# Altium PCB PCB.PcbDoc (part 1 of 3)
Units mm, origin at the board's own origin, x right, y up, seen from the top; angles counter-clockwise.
Board outline 120 x 100 mm, 4 copper layers (Top Layer, Mid-Layer 1, Mid-Layer 2, Bottom Layer); 85 components, 69 nets, 423 pads, 4470 vias.
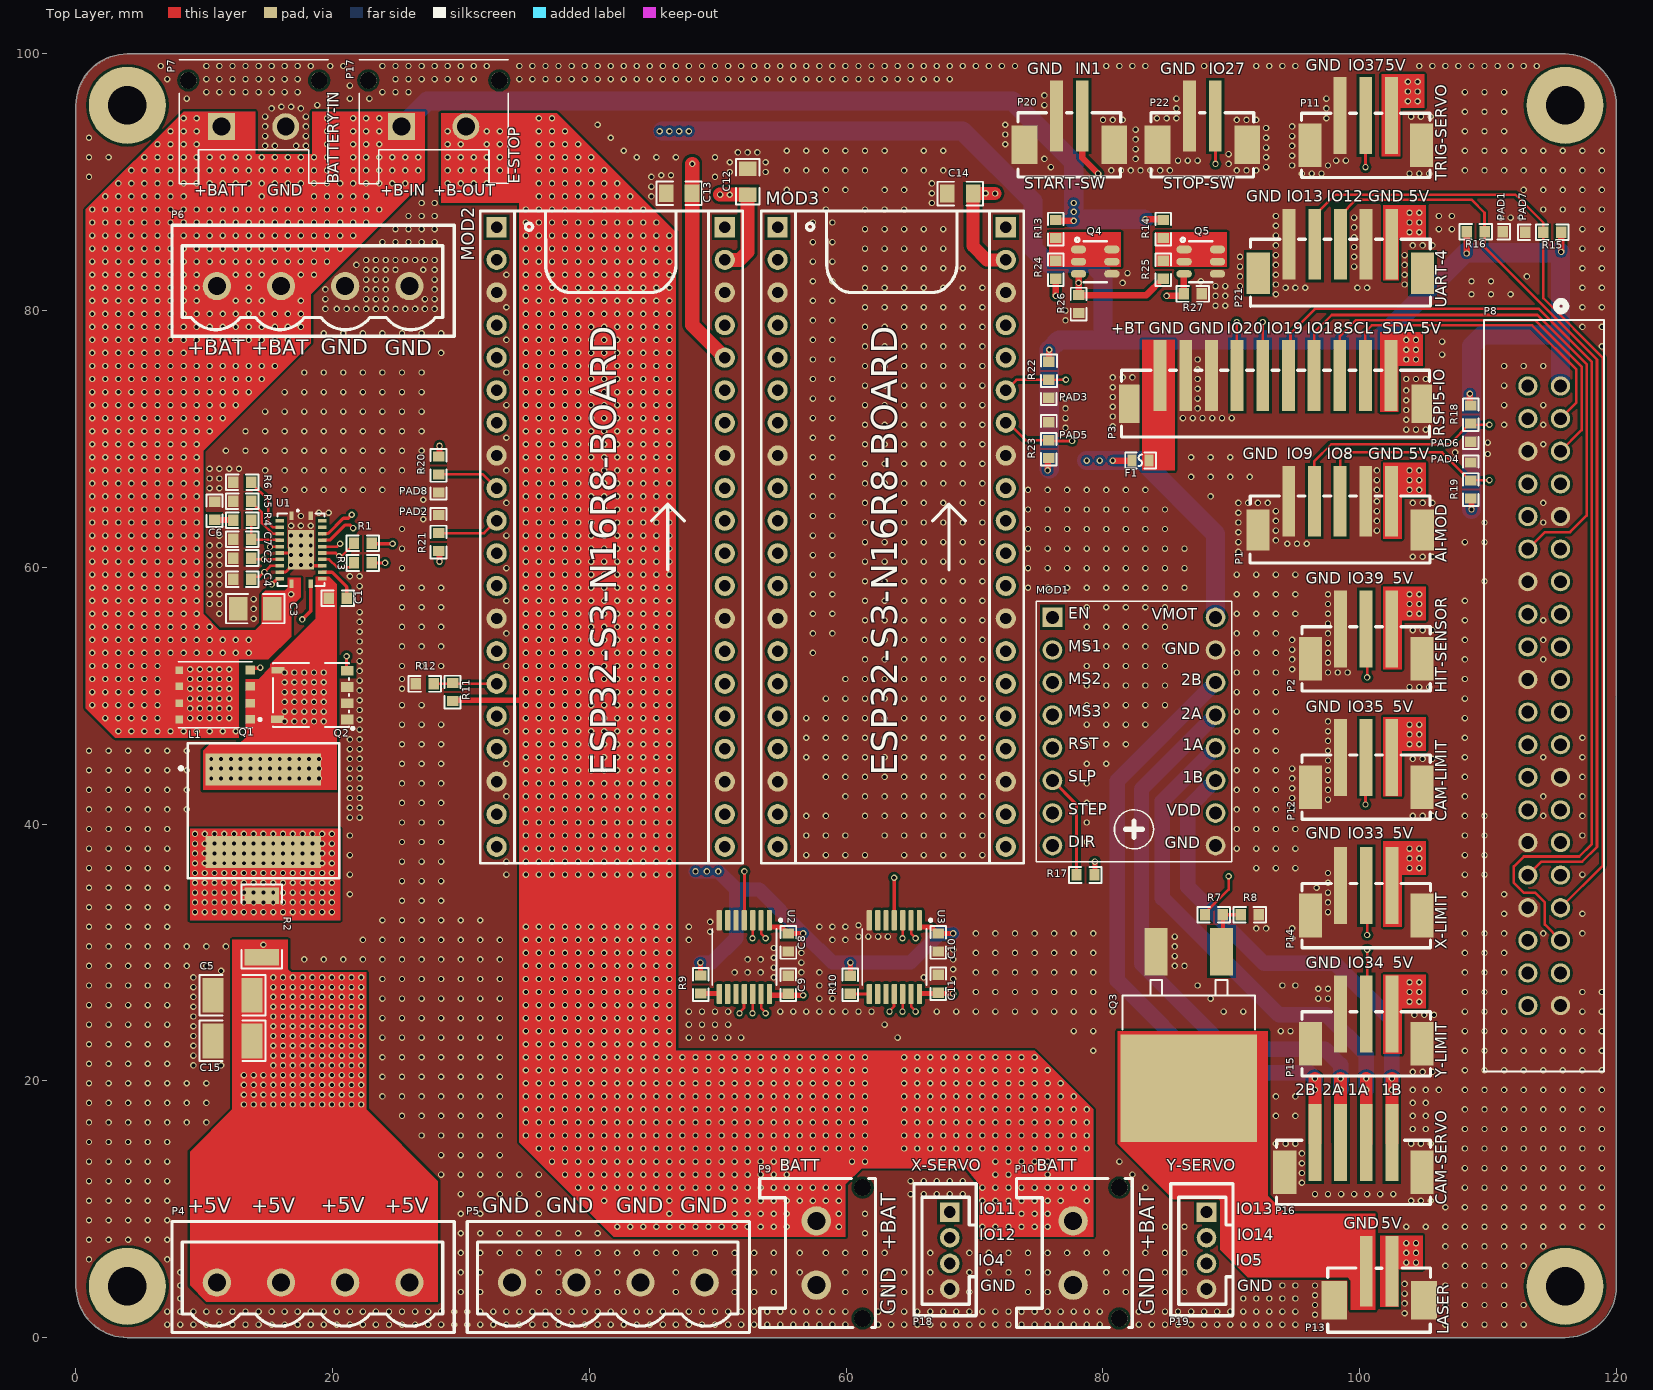
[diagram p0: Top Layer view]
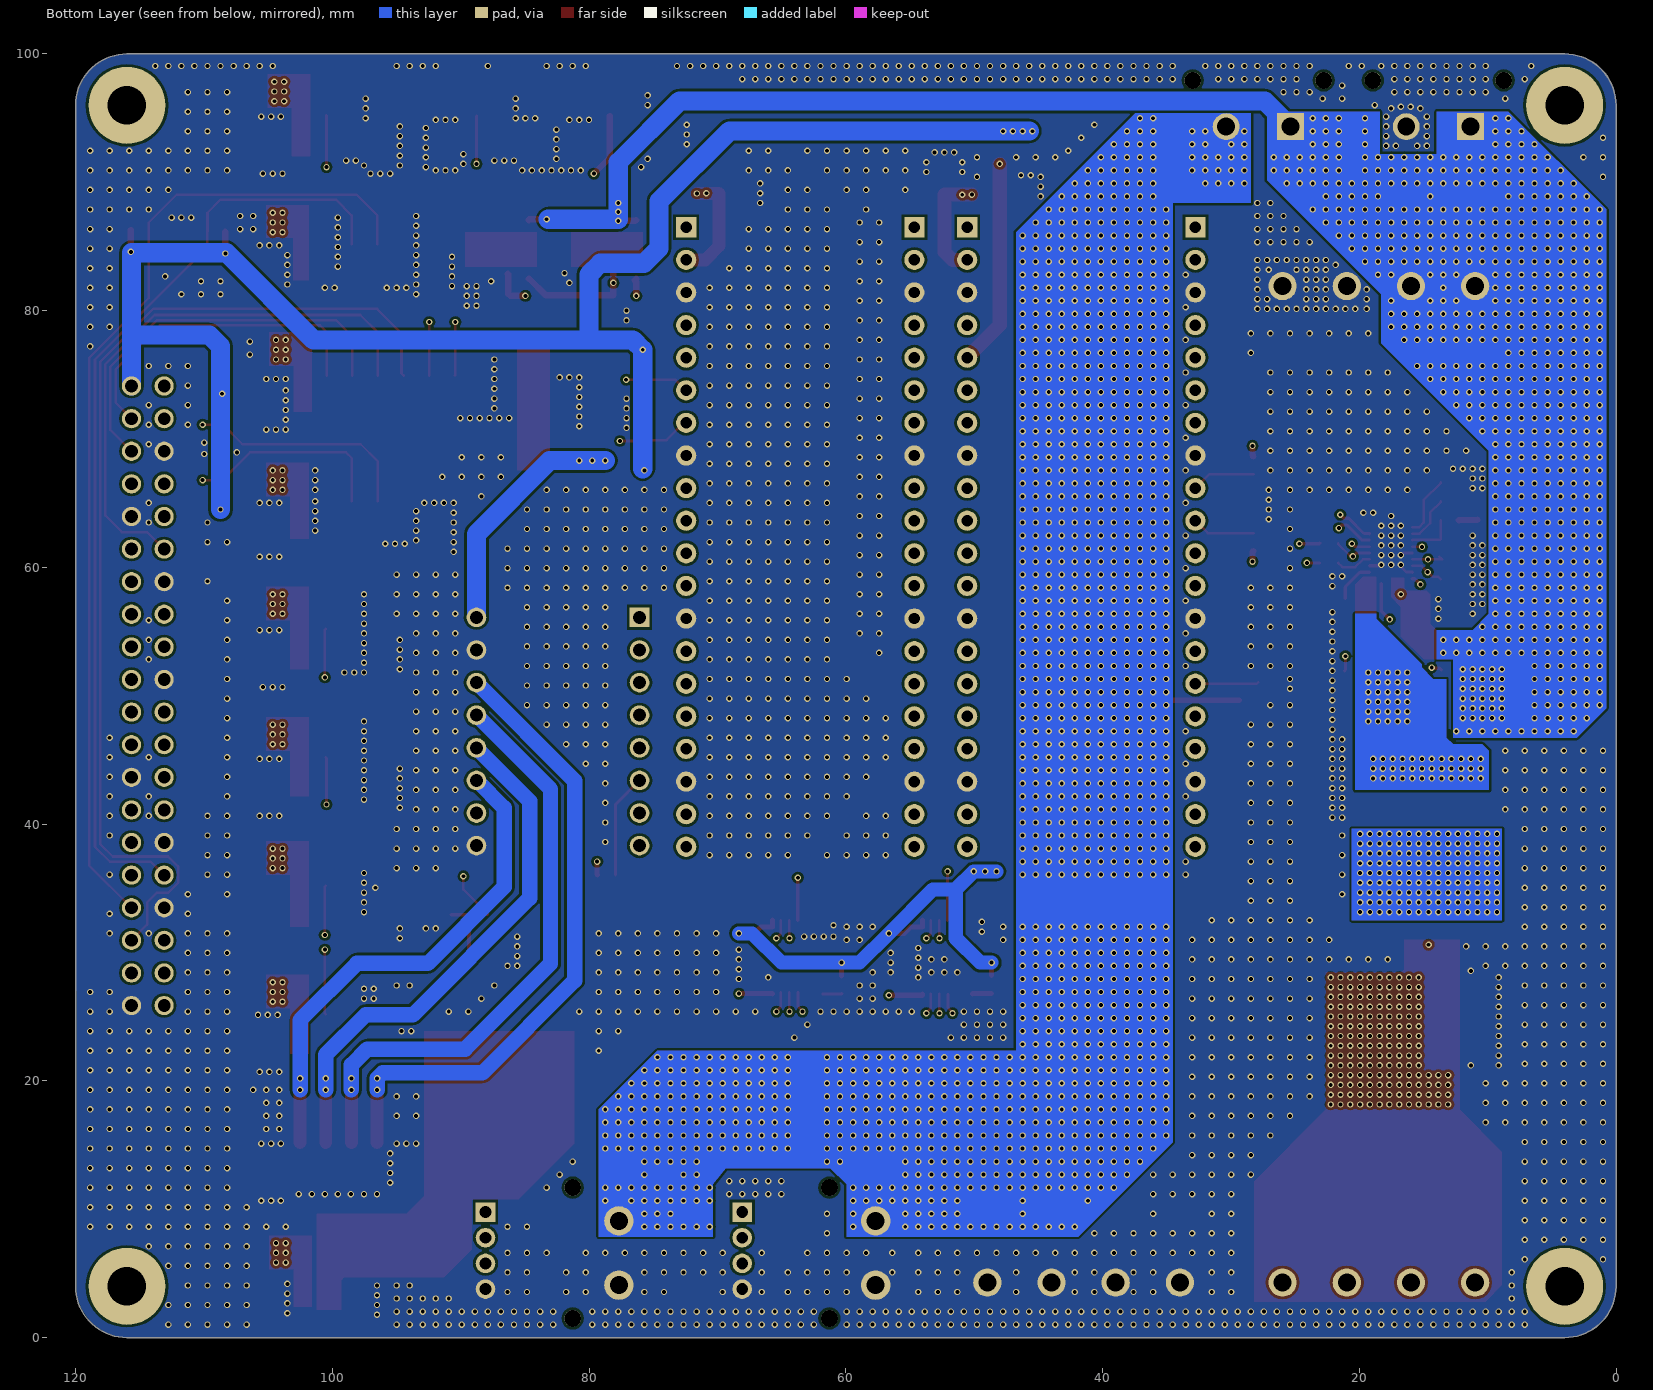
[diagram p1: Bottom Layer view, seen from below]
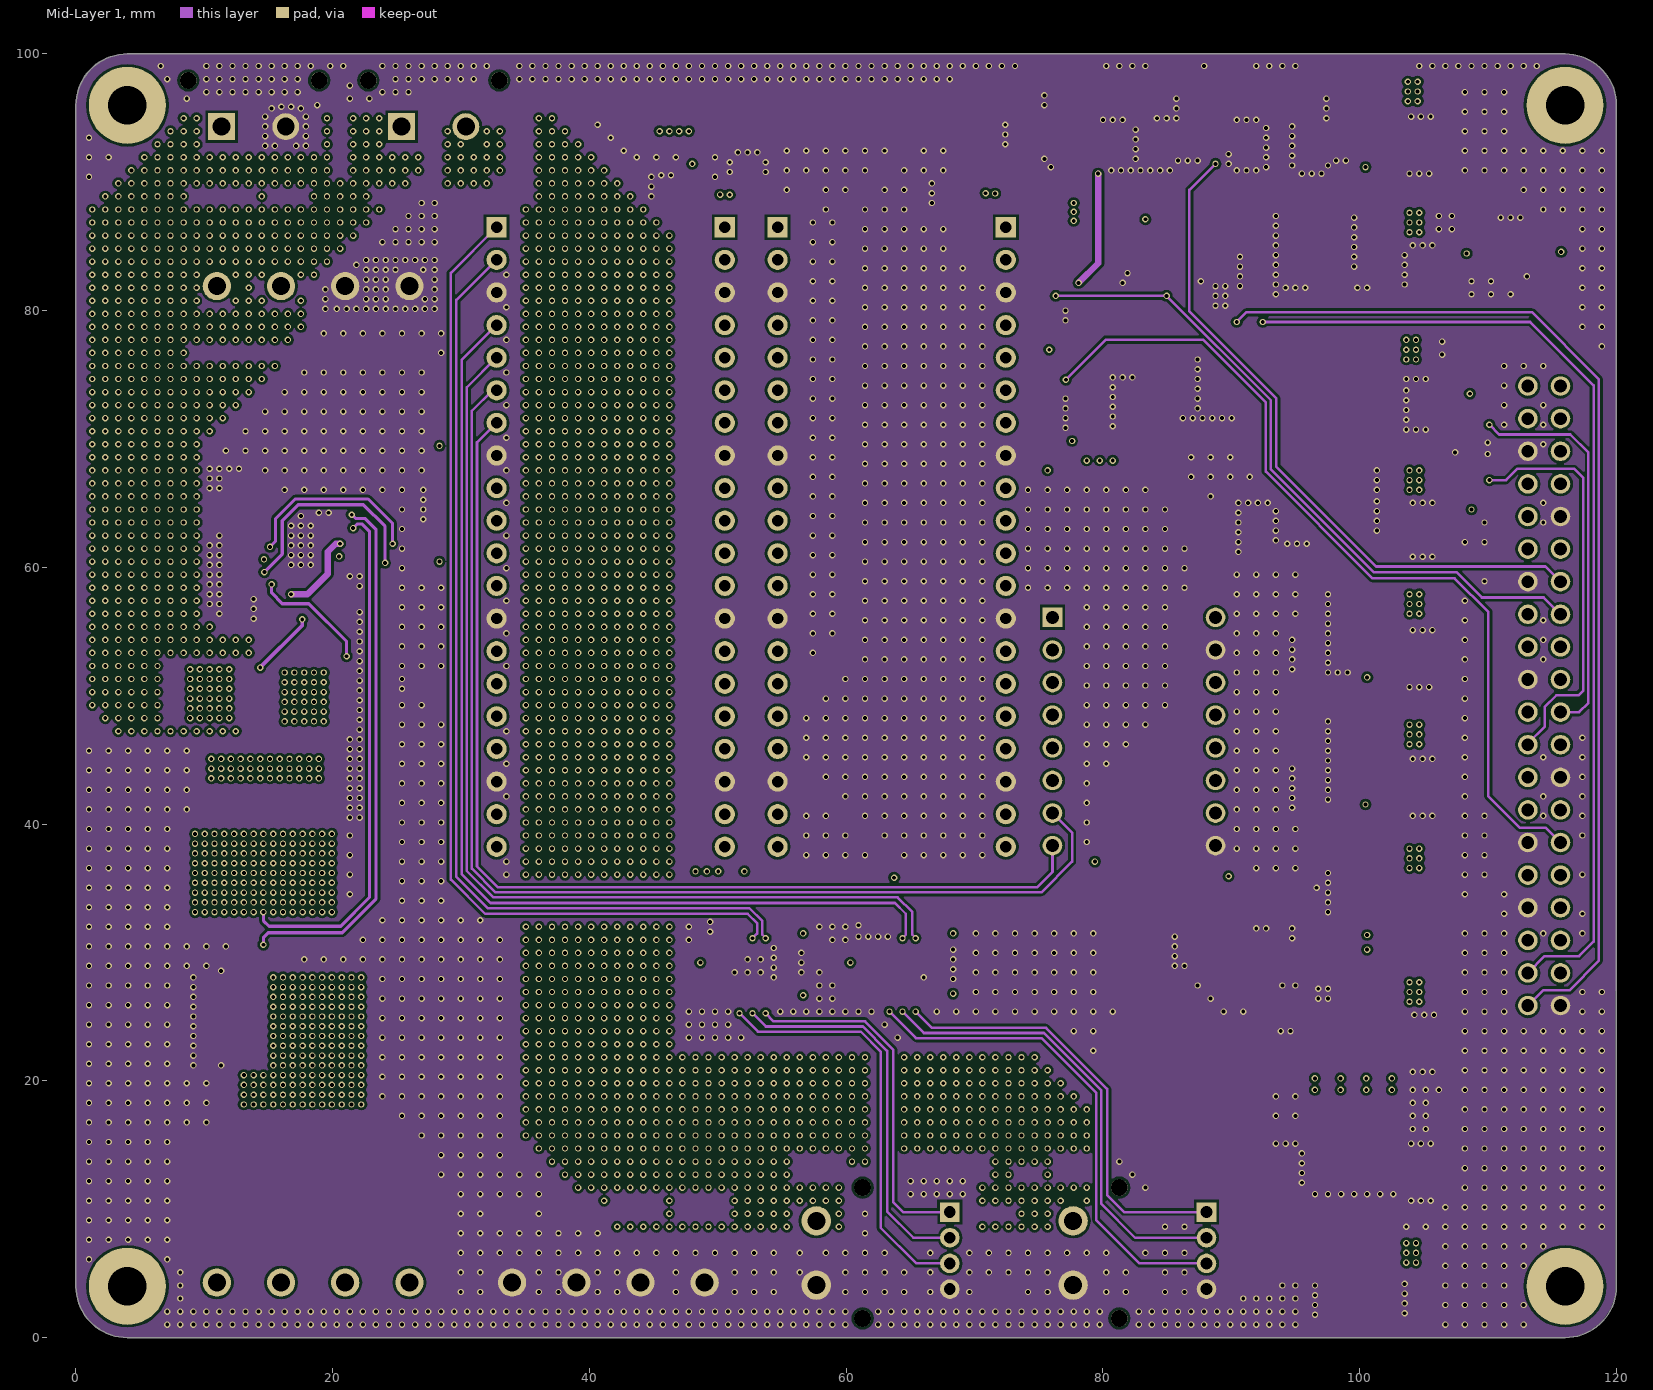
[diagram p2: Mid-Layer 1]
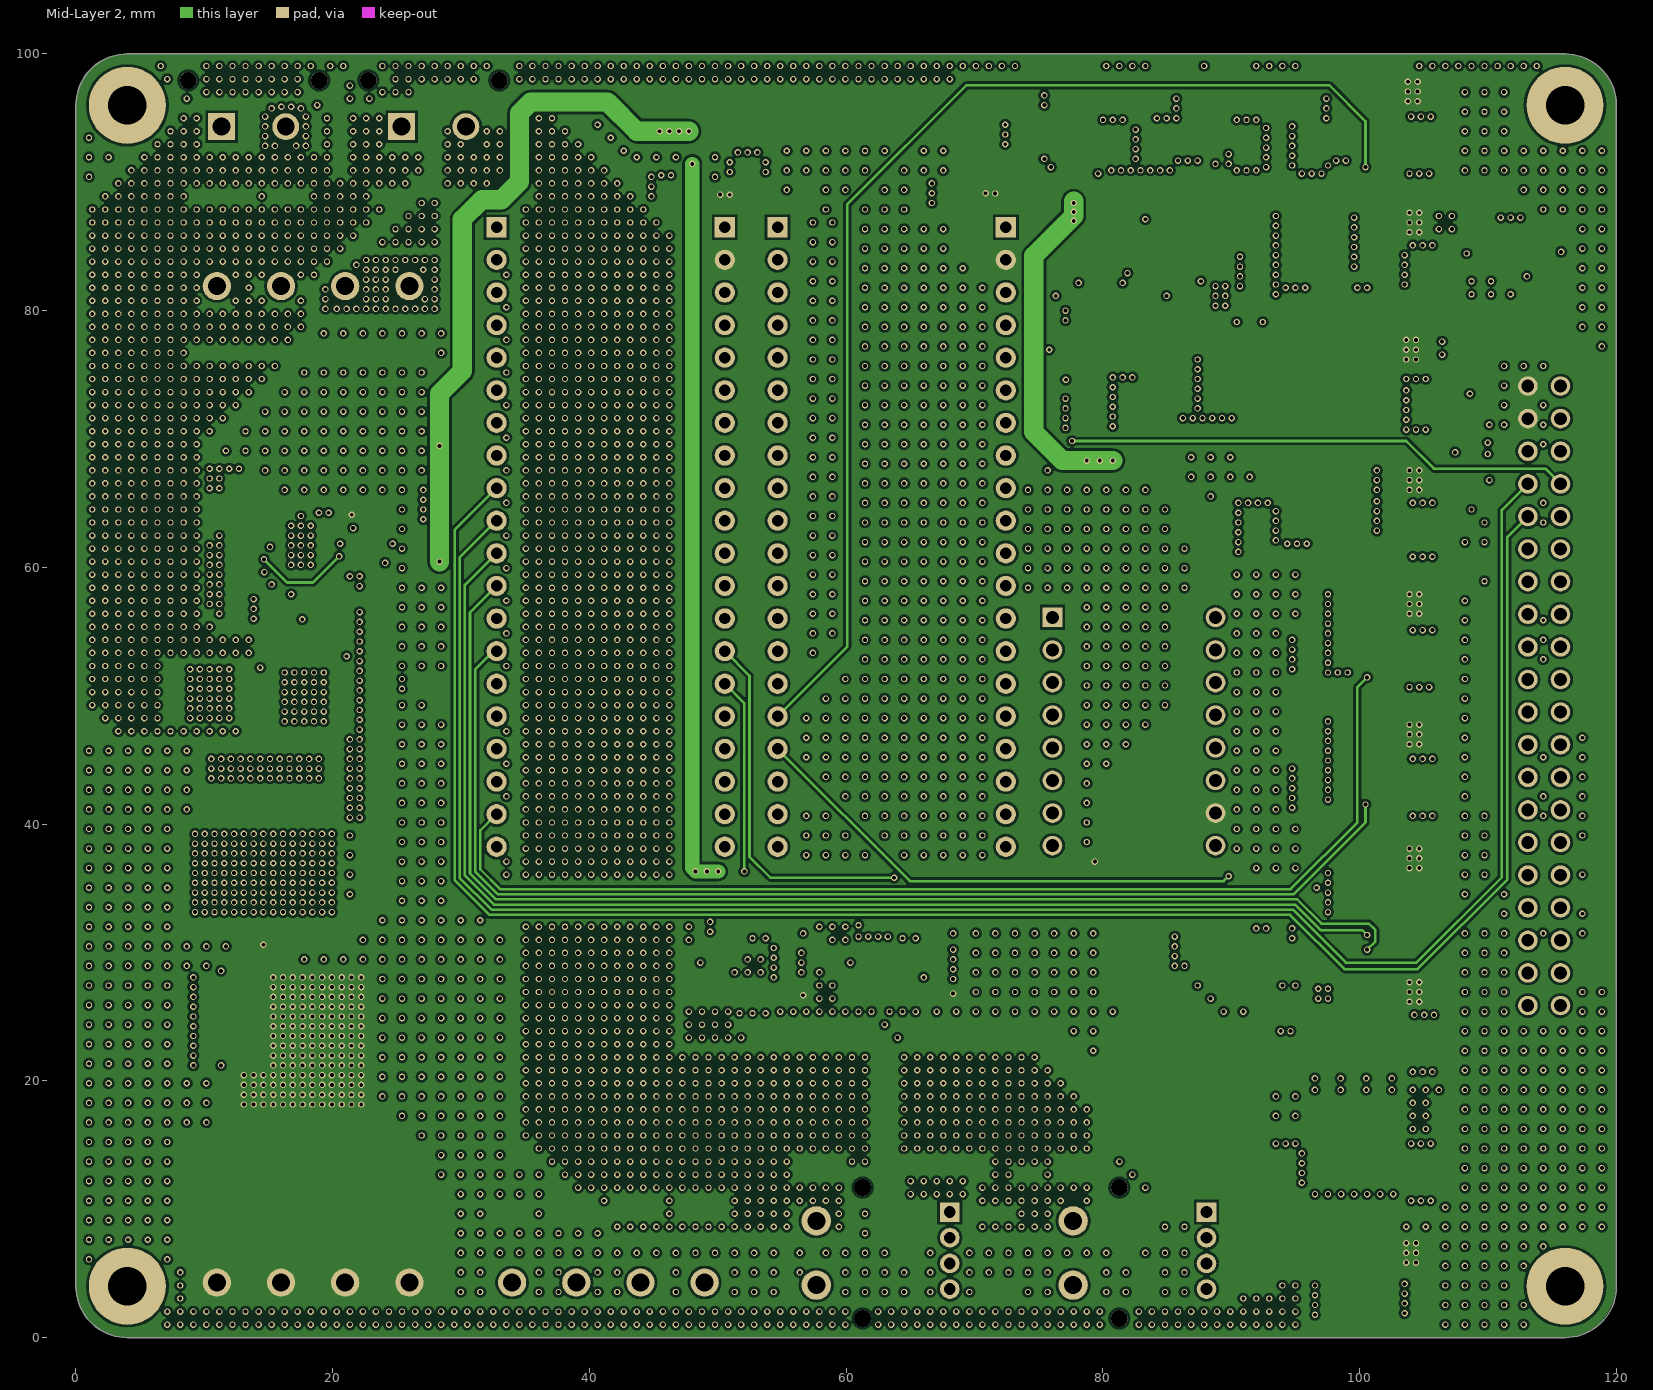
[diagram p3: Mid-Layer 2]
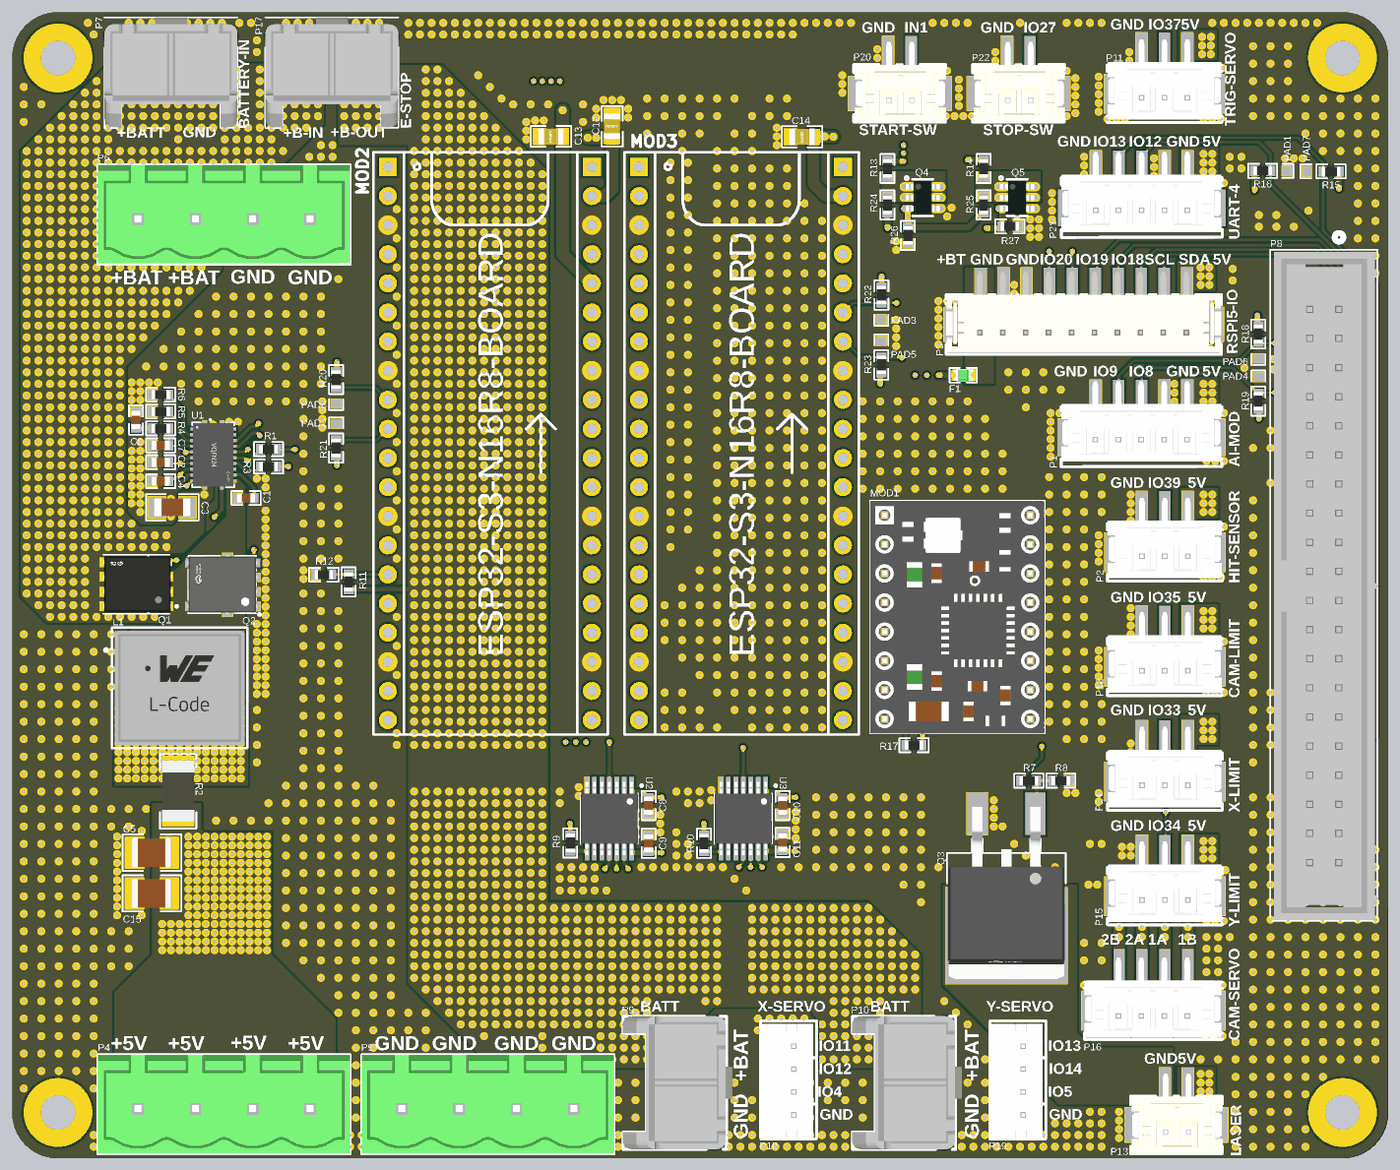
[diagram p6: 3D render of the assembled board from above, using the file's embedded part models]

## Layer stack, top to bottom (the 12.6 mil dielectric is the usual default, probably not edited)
Top Solder: solder mask 0.0102, Solder Resist, Dk 3.5
Top Layer: signal copper 0.0356
Dielectric 1: dielectric 0.32, FR-4, Dk 4.8
Mid-Layer 1: signal copper 0.0356
Dielectric2: dielectric 0.32, FR-4, Dk 4.8
Mid-Layer 2: signal copper 0.0356
Dielectric3: dielectric 0.32, FR-4, Dk 4.8
Bottom Layer: signal copper 0.0356
Bottom Solder: solder mask 0.0102, Solder Resist, Dk 3.5

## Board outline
0,4 0,96 cw(c4,96) 4,100 116,100 cw(c116,96) 120,96 120,4 cw(c116,4) 116,0 4,0 cw(c4,4)

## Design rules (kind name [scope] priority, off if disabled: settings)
Clearance [All] p1: gap=0.2 ignorepadtopadclearanceinfootprint=FALSE except(0: Arc-Hole Track-Hole SMDPad-Hole THPad-Hole Via-Hole Fill-Hole Poly-Hole Region-Hole Text-Hole; 0.18: Fill-Fill Fill-Poly Fill-Region Poly-Poly Poly-Region Region-Region)
HoleSize [All] p1: absolutevalues=TRUE maxlimit=5 minlimit=0.025 maxpercent=80.000 minpercent=20.000
MinimumSolderMaskSliver [All] p1: minsoldermaskwidth=0.007
PlaneClearance [All] p1: clearance=0.4
PolygonConnect [InNet('GND') vs InNet('GND')] p1: connectstyle=Direct reliefconductorwidth=0.254 reliefentries=4 polygonreliefangle="90 Angle" airgapwidth=0.254
PolygonConnect PolygonConnect_1 [InNet('+5V') vs InNet('+5V')] p2: connectstyle=Direct reliefconductorwidth=0.254 reliefentries=4 polygonreliefangle="90 Angle" airgapwidth=0.254
RoutingVias [All] p1: holewidth=0.3 width=0.5 viastyle="Through Hole" minholewidth=0.2 minwidth=0.5 maxholewidth=0.4 maxwidth=0.5
SilkToSilkClearance [All] p1: silktosilkclearance=0.1
SilkToSolderMaskClearance [IsPad] p1: minsilkscreentomaskgap=0.02 clearancetoexposedcopper=TRUE
SolderMaskExpansion [All] p1: expansion=0.102
Width [All] p1: maxlimit=3 minlimit=0.2 preferedwidth=0.254
25 further rules are at their usual default settings.

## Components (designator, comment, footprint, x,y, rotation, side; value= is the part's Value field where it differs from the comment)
C1 "0.1uF/50V" CAP_SMD_0603 20.396,57.607 r0 top
C2 "0.1uF/50V" CAP_SMD_0603 12.954,60.731 r180 top
C3 "4.7uF/100V" CAP_SMD_1206 13.97,56.794 r0 top
C4 "2.2uF" CAP_SMD_0603 12.954,59.08 r0 top
C5 "47uF/16V" CAP_SMD_1210 12.192,26.67 r0 top
C6 "1.5nF" CAP_SMD_0603 10.795,64.414 r90 top
C7 "56pF" CAP_SMD_0603 12.954,62.205 r180 top
C8 "0.1uF/50V" CAP_SMD_0603 55.499,30.785 r90 top
C9 "0.1uF/50V" CAP_SMD_0603 55.499,27.483 r270 top
C10 "0.1uF/50V" CAP_SMD_0603 67.183,30.785 r90 top
C11 "0.1uF/50V" CAP_SMD_0603 67.183,27.559 r270 top
C12 "10uF/16V" CAP_SMD_0805 52.324,90.043 r270 top
C13 "10uF/16V" CAP_SMD_0805 46.99,89.154 r0 top
C14 "10uF/16V" CAP_SMD_0805 68.885,89.129 r0 top
C15 "47uF/16V" CAP_SMD_1210 12.192,23.114 r0 top
F1 "1A/50V" FUSE_SMD_0603 82.931,68.326 r180 top
L1 "1.2uH/23.6A" "IND_SMD_7.90mm x 7.60mm" 14.605,41.046 r0 top
MOD1 "A4988_Module" A4988_Stepper_Motor_Module 82.423,47.219 r0 top
MOD2 "ESP32-S3-Pico-Module" ESP32-S3-PICO_Module 41.656,62.37 r0 top
MOD3 "ESP32-S3-Pico-Module" ESP32-S3-PICO_Module 63.55,62.37 r0 top
P1 "AI MOD" CONN_Header_SMD_Vertical_5P_2MM_B5B-PH-SM4-TB 98.477,64.043 r180 top
P2 "HIT_SENSOR" CONN_Header_SMD_Vertical_3P_2MM_B3B-PH-SM4-TB 100.508,54.043 r180 top
P3 "IO" CONN_Header_SMD_Vertical_10P_2MM_B10B-PH-SM4-TB 93.451,73.855 r180 top
P4 "5V" CONN_Terminal_Block_Header_4P_Vertical__THT_5.00mm_1755532 18.477,4.293 r0 top
P5 "5V" CONN_Terminal_Block_Header_4P_Vertical__THT_5.00mm_1755532 41.477,4.293 r0 top
P6 "BATT" CONN_Terminal_Block_Header_4P_Vertical__THT_5.00mm_1755532 18.477,81.915 r0 top
P7 "BATT" CONN_HEADER_VERT_2POS_5MM_1-1376382-2 13.843,96.139 r0 top
P8 "RPI-5" CONN_HEADERTHT_IDE_40P_2.54mm 114.376,50 r270 top
P9 "BATT" CONN_HEADER_VERT_2POS_5MM_2-1376382-3 59.477,6.593 r90 top
P10 "BATT" CONN_HEADER_VERT_2POS_5MM_2-1376382-3 79.477,6.593 r90 top
P11 "TRIGGER_SERVO" CONN_Header_SMD_Vertical_3P_2MM_B3B-PH-SM4-TB 100.476,94.043 r180 top
P12 "CAM-LIMIT" CONN_Header_SMD_Vertical_3P_2MM_B3B-PH-SM4-TB 100.508,44.043 r180 top
P13 "LASER" CONN_Header_SMD_Vertical_2P_2MM_B2B-PH-SM4-TB 101.514,4.043 r180 top
P14 "X-LIMIT" CONN_Header_SMD_Vertical_3P_2MM_B3B-PH-SM4-TB 100.514,34.043 r180 top
P15 "Y-LIMIT" CONN_Header_SMD_Vertical_3P_2MM_B3B-PH-SM4-TB 100.514,24.043 r180 top
P16 "CAM_SERVO" CONN_Header_SMD_Vertical_4P_2MM_B4B-PH-SM4-TB 99.517,14.043 r180 top
P17 "ESTOP" CONN_HEADER_VERT_2POS_5MM_1-1376382-2 27.875,96.139 r0 top
P18 "X-SERVO" CONN_Header_Through_Hole_4P_2MM_B4B-PH-K 68.072,6.782 r270 top
P19 "Y-SERVO" CONN_Header_Through_Hole_4P_2MM_B4B-PH-K 88.072,6.782 r270 top
P20 "Start" CONN_Header_SMD_Vertical_2P_2MM_B2B-PH-SM4-TB 77.389,94.043 r180 top
P21 "UART4" CONN_Header_SMD_Vertical_5P_2MM_B5B-PH-SM4-TB 98.501,84.043 r180 top
P22 "Stop" CONN_Header_SMD_Vertical_2P_2MM_B2B-PH-SM4-TB 87.752,94.043 r180 top
PAD1 "PAD" PAD_SMD_0.8MMX0.9MM 111.142,86.157 r0 top
PAD2 "PAD" PAD_SMD_0.8MMX0.9MM 28.245,64.076 r90 top
PAD3 "PAD" PAD_SMD_0.8MMX0.9MM 75.795,73.214 r270 top
PAD4 "PAD" PAD_SMD_0.8MMX0.9MM 108.661,68.166 r90 top
PAD5 "PAD" PAD_SMD_0.8MMX0.9MM 75.795,71.318 r90 top
PAD6 "PAD" PAD_SMD_0.8MMX0.9MM 108.661,69.799 r270 top
PAD7 "PAD" PAD_SMD_0.8MMX0.9MM 112.903,86.106 r180 top
PAD8 "PAD" PAD_SMD_0.8MMX0.9MM 28.245,65.845 r270 top
Q1 "CSD18534Q5A" VSONP-8_5MMx6MM 12.213,50.088 r180 top
Q2 "NTMFS5C670NLT1G" DFN-5_5MMx6MM 18.415,50.063 r90 top
Q3 "IRF520SPBF" D2PAK 86.69,24.75 r180 top
Q4 "SIL05N06A-TP" SOT-23-6 79.4,83.82 r0 top
Q5 "SIL05N06A-TP" SOT-23-6 87.63,83.82 r0 top
R1 "24.3K" RES_SMD_0603 22.352,61.874 r0 top
R2 "5mR" RES_SMD_2010 14.478,32.029 r270 top
R3 "100K" RES_SMD_0603 22.352,60.35 r0 top
R4 "5.23K" RES_SMD_0603 12.954,63.679 r180 top
R5 "21K" RES_SMD_0603 12.954,65.153 r180 top
R6 "40.2K" RES_SMD_0603 12.954,66.627 r180 top
R7 "1K" RES_SMD_0603 88.646,32.944 r180 top
R8 "100K" RES_SMD_0603 91.44,32.944 r180 top
R9 "10K" RES_SMD_0603 48.666,27.508 r90 top
R10 "10K" RES_SMD_0603 60.325,27.483 r90 top
R11 "22K" RES_SMD_0603 29.337,50.292 r270 top
R12 "2K" RES_SMD_0603 27.178,50.927 r0 top
R13 "10K" RES_SMD_0603 76.327,86.36 r90 top
R14 "10K" RES_SMD_0603 84.709,86.36 r90 top
R15 "10K" RES_SMD_0603 115.003,86.106 r0 top
R16 "10K" RES_SMD_0603 109.042,86.157 r180 top
R17 "10K" RES_SMD_0603 78.638,36.043 r0 top
R18 "10K" RES_SMD_0603 108.661,71.907 r90 top
R19 "10K" RES_SMD_0603 108.661,66.065 r270 top
R20 "10K" RES_SMD_0603 28.245,67.945 r90 top
R21 "10K" RES_SMD_0603 28.245,61.976 r270 top
R22 "10K" RES_SMD_0603 75.796,75.314 r90 top
R23 "10K" RES_SMD_0603 75.795,69.218 r270 top
R24 "110K" RES_SMD_0603 76.327,83.185 r90 top
R25 "110K" RES_SMD_0603 84.709,83.185 r270 top
R26 "10K" RES_SMD_0603 78.105,80.518 r90 top
R27 "10K" RES_SMD_0603 86.995,81.306 r180 top
U1 "LM5149RGYR" VQFN-24_3.5MMx5.5MM 17.538,61.376 r0 top
U2 "TXS0104EPWR" TSSOP-14 52.07,29.642 r270 top
U3 "TXS0104EPWR" TSSOP-14 63.754,29.642 r270 top

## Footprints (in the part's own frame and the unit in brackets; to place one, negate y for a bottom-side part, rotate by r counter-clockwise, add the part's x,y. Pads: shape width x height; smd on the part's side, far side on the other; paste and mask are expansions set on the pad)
A4988_Stepper_Motor_Module [mm]
  rect 1.53x1.53 hole 1.02: 1(-6.35,8.89)
  round 1.53 hole 1.02: 2(-6.35,6.35) 3(-6.35,3.81) 4(-6.35,1.27) 5(-6.35,-1.27) 6(-6.35,-3.81) 7(-6.35,-6.35) 8(-6.35,-8.89) 9(6.35,-8.89) 10(6.35,-6.35) 11(6.35,-3.81) 12(6.35,-1.27) 13(6.35,1.27) 14(6.35,3.81) 15(6.35,6.35) 16(6.35,8.89)
  silkscreen extent -7.62,-10.16 7.62,10.16, body extent -7.62,-10.16 7.62,10.16, height 6.09
CAP_SMD_0603 [mm]
  rect 0.8x0.9 smd paste+0 mask+0.051: 1(-0.7,0) 2(0.7,0)
  silkscreen extent -1.27,-0.61 1.27,0.61, body extent -0.8,-0.4 0.8,0.4, height 0.95
CAP_SMD_0805 [mm]
  rect 1.133x1.377 smd paste-100 mask+0.051: 1(-1,0) 2(1,0)
  silkscreen extent -1.76,-0.92 1.76,0.92, body extent -1.1,-0.74 1.1,0.71, height 0.88
CAP_SMD_1206 [mm]
  rect 1.44x1.82 smd: 1(-1.336,0) 2(1.336,0)
  silkscreen extent -2.28,-1.14 2.28,1.15, body extent -1.6,-0.8 1.6,0.8, height 1.8
CAP_SMD_1210 [mm]
  rect 1.635x2.7 smd paste-100 mask+0.051: 1(-1.517,0) 2(1.517,0)
  silkscreen extent -2.56,-1.58 2.56,1.58, body extent -1.75,-1.3 1.65,1.3, height 1.5
CONN_Header_SMD_Vertical_2P_2MM_B2B-PH-SM4-TB [mm]
  rect 1x5.5 smd paste+0 mask+0.051: 1(-1,-1.125) 2(1,-1.125)
  rect 2x3 smd paste+0 mask+0.051: MP(-3.5,1.125) MP(3.5,1.125)
  silkscreen extent -4,-1.38 4,3.63, body extent -4.04,-3.35 3.91,3.65, height 6.75
CONN_Header_SMD_Vertical_3P_2MM_B3B-PH-SM4-TB [mm]
  rect 1x6 smd paste+0 mask+0.051: 1(-2,-1.163) 2(0,-1.163) 3(2,-1.163)
  rect 1.8x3.4 smd paste+0 mask+0.051: MP(-4.35,1.163) MP(4.35,1.163)
  silkscreen extent -5,-1.34 5,3.66, body extent -4.98,-3.6 4.97,3.4, height 6.8
CONN_Header_SMD_Vertical_4P_2MM_B4B-PH-SM4-TB [mm]
  rect 1x6 smd paste+0 mask+0.051: 1(-2.997,-1.158) 2(-0.997,-1.158) 3(1.003,-1.158) 4(3.001,-1.158)
  rect 1.8x3.4 smd paste+0 mask+0.051: MP(-5.349,1.158) MP(5.349,1.158)
  silkscreen extent -6,-1.33 6,3.67, body extent -5.92,-3.48 6.03,3.52, height 6.75
CONN_Header_SMD_Vertical_5P_2MM_B5B-PH-SM4-TB [mm]
  rect 1x5.5 smd paste+0 mask+0.051: 1(-4,-1.125) 2(-2,-1.125) 3(0,-1.125) 4(2,-1.125) 5(4,-1.125)
  rect 1.8x3.2 smd paste+0 mask+0.051: MP(-6.4,1.125) MP(6.4,1.125)
  silkscreen extent -7.01,-1.53 7.01,3.7, body extent -6.95,-3.76 7,3.24, height 6.75
CONN_Header_SMD_Vertical_10P_2MM_B10B-PH-SM4-TB [mm]
  rect 1x5.5 smd paste+0 mask+0.051: 1(-9,-1.099) 2(-7,-1.099) 3(-5,-1.099) 4(-3,-1.099) 5(-1,-1.099) 6(1,-1.099) 7(3.002,-1.101) 8(5.002,-1.101) 9(7,-1.099) 10(9,-1.099)
  rect 1.6x3 smd paste+0 mask+0.051: MP(-11.4,1.101) MP(11.4,1.101)
  silkscreen extent -12,-1.5 12,3.7, body extent -11.97,-3.49 12.03,3.51, height 6.7
CONN_Header_Through_Hole_4P_2MM_B4B-PH-K [mil]
  rect 60x60 hole 36 paste+0 mask+2: 1(-118.11,0)
  round 60 hole 36 paste+0 mask+2: 2(-39.37,0) 3(39.37,0) 4(118.11,0)
  silkscreen extent -205,-110 200,81, body extent -195,-107 195,70, height 240
CONN_HEADER_VERT_2POS_5MM_1-1376382-2 [mm]
  rect 2.1x2.1 hole 1.4: 1(-2.5,-1.8)
  round 2.1 hole 1.4: 2(2.5,-1.8)
  round 1.3 hole 1.3 unplated: ""(-5.1,1.8) ""(5.1,1.8)
  silkscreen extent -5.8,-6.25 5.8,3.4, body extent -5.79,-6.2 5.81,3.4, height 14.2
CONN_HEADER_VERT_2POS_5MM_2-1376382-3 [mm]
  round 2.3 hole 1.4 paste+0 mask+0.051: 1(2.5,1.8) 2(-2.5,1.8)
  round 1.3 hole 1.3 unplated paste+0: ""(-5.1,-1.8) ""(5.1,-1.8)
  silkscreen extent -5.8,-2.8 5.8,6.2, body extent -5.79,-3.35 5.81,6.25, height 14.2
CONN_HEADERTHT_IDE_40P_2.54mm [mil]
  round 59 / inner round 60 / far side round 59 hole 39 paste-29.5 mask+0: 1(-950,50) 2(-950,-50) 3(-850,50) 4(-850,-50) 5(-750,50) 6(-750,-50) 7(-650,50) 8(-650,-50) 9(-550,50) 10(-550,-50) 11(-450,50) 12(-450,-50) 13(-350,50) 14(-350,-50) 15(-250,50) 16(-250,-50) 17(-150,50) 18(-150,-50) 19(-50,50) 20(-50,-50) 21(50,50) 22(50,-50) 23(150,50) 24(150,-50) 25(250,50) 26(250,-50) 27(350,50) 28(350,-50) 29(450,50) 30(450,-50) 31(550,50) 32(550,-50) 33(650,50) 34(650,-50) 35(750,50) 36(750,-50) 37(850,50) 38(850,-50) 39(950,50) 40(950,-50)
  silkscreen extent -1210,-184 1152,184, body extent -1145,-172 1150,186, height 354
CONN_Terminal_Block_Header_4P_Vertical__THT_5.00mm_1755532 [mm]
  round 2.2 hole 1.4 paste+0 mask+0.05: 1(-7.5,0) 2(-2.5,0) 3(2.5,0) 4(7.5,0)
  silkscreen extent -11,-3.9 11,4.75, body extent -11,-3.83 11,4.74, height 12.25
D2PAK [mm]
  rect 1.8x3.7 smd paste+0 mask+0.051: 1(-2.54,-5.321) 3(2.54,-5.321)
  rect 10.608x8.4 smd paste+0 mask+0.051: 2(0,5.321)
  silkscreen extent -5.18,-3.12 5.18,0.75, body extent -5.1,-5.91 5.1,9.11, height 4.5
DFN-5_5MMx6MM [mm]
  rect 0.75x1 smd paste+0 mask+0.051: 1(-1.914,-2.722) 2(-0.644,-2.722) 3(0.626,-2.722) 4(1.896,-2.722)
  rect 0.5x1 smd paste+0 mask+0.051: 5(1.914,2.671)
  rect 0.6x1 smd paste+0 mask+0.051: 6(-1.896,2.722)
  Top Layer region: -2.296,-1.24 -2.296,-0.815 -2.791,-0.815 -2.791,0.09 -2.296,0.09 -2.296,3.29 -1.546,3.29 -1.546,2.79 1.514,2.79 1.514,3.29 2.264,3.29 2.264,0.09 2.759,0.09 2.759,-0.815 2.264,-0.815 2.264,-1.24
  silkscreen extent -2.71,-3.25 2.49,3.05, body extent -2.57,-2.97 2.58,3.18, height 1.05
ESP32-S3-PICO_Module [mil]
  rect 62x62 hole 35 paste+0 mask+2: 1(-349.99,950) 40(349.99,950)
  round 62 hole 35 paste+0 mask+2: 2(-349.99,850) 3(-349.99,750) 4(-349.99,650) 5(-349.99,550) 6(-349.99,450) 7(-349.99,350) 8(-349.99,250) 9(-349.99,150) 10(-349.99,50) 11(-349.99,-50) 12(-349.99,-150) 13(-349.99,-250) 14(-349.99,-350) 15(-349.99,-450) 16(-349.99,-550) 17(-349.99,-650) 18(-349.99,-750) 19(-349.99,-850) 20(-349.99,-950) 21(349.99,-950) 22(349.99,-850) 23(349.99,-750) 24(349.99,-650) 25(349.99,-550) 26(349.99,-450) 27(349.99,-350) 28(349.99,-250) 29(349.99,-150) 30(349.99,-50) 31(349.99,50) 32(349.99,150) 33(349.99,250) 34(349.99,350) 35(349.99,450) 36(349.99,550) 37(349.99,650) 38(349.99,750) 39(349.99,850)
  silkscreen extent -400,-1000 405,1000
FUSE_SMD_0603 [mm]
  rect 0.7x0.95 smd paste-100 mask+0.051: 1(-0.675,0) 2(0.675,0)
  silkscreen extent -1.19,-0.64 1.19,0.64, body extent -0.91,-0.52 0.89,0.52, height 0.45
"IND_SMD_7.90mm x 7.60mm" [mm]
  rect 9x2.5 smd: 1(0,3.2) 2(0,-3.2)
  silkscreen extent -6.55,-5.25 5.9,5.25, body extent -5.65,-5 5.65,5, height 10
PAD_SMD_0.8MMX0.9MM [mm]
  rect 0.8x0.9 smd paste+0 mask+0.051: 1(0,0)
  silkscreen extent -0.4,-0.61 0.57,0.61
RES_SMD_0603 [mm]
  rect 0.8x0.9 smd paste+0 mask+0.051: 1(-0.7,0) 2(0.7,0)
  silkscreen extent -1.27,-0.61 1.27,0.61, body extent -0.8,-0.4 0.8,0.4, height 0.45
RES_SMD_2010 [mm]
  rect 1.283x2.7 smd paste-100 mask+0.051: 1(-2.391,0) 2(2.391,0)
  silkscreen extent -3.26,-1.58 3.26,1.58, body extent -2.67,-1.4 2.67,1.4, height 0.89
SOT-23-6 [mm]
  oval 1.2x0.6 smd paste-0.05: 1(-1.3,0.95) 2(-1.3,0) 3(-1.3,-0.95) 4(1.3,-0.95) 5(1.3,0) 6(1.3,0.95)
  silkscreen extent -1.55,-1.6 0.9,1.85, body extent -1.5,-1.5 1.5,1.5, height 1.3
TSSOP-14 [mm]
  rrect25% 1.57x0.41 smd mask+0.04: 1(-2.87,1.95) 2(-2.87,1.3) 3(-2.87,0.65) 4(-2.87,0) 5(-2.87,-0.65) 6(-2.87,-1.3) 7(-2.87,-1.95) 8(2.87,-1.95) 9(2.87,-1.3) 10(2.87,-0.65) 11(2.87,0) 12(2.87,0.65) 13(2.87,1.3) 14(2.87,1.95)
  silkscreen extent -2.97,-2.5 2.2,2.92, body extent -3.2,-2.5 3.2,2.5, height 1.2
VQFN-24_3.5MMx5.5MM [mm]
  rect 0.336x0.665 smd paste+0 mask+0.051: 1(-0.75,2.658) 12(-0.75,-2.658) 13(0.75,-2.658) 24(0.75,2.658)
  rect 0.665x0.28 smd paste+0 mask+0.051: 2(-1.658,2.25) 3(-1.658,1.75) 4(-1.658,1.25) 5(-1.658,0.75) 6(-1.658,0.25) 7(-1.658,-0.25) 8(-1.658,-0.75) 9(-1.658,-1.25) 10(-1.658,-1.75) 11(-1.658,-2.25) 14(1.658,-2.25) 15(1.658,-1.75) 16(1.658,-1.25) 17(1.658,-0.75) 18(1.658,-0.25) 19(1.658,0.25) 20(1.658,0.75) 21(1.658,1.25) 22(1.658,1.75) 23(1.658,2.25)
  rect 2.05x3.1 smd paste+0 mask+0.051: 25(0,0)
  silkscreen extent -1.83,-2.83 1.83,3.12, body extent -1.76,-2.76 1.76,2.76, height 1
VSONP-8_5MMx6MM [mm]
  rect 0.75x0.675 smd paste-1: 1(-1.376,1.918) 2(-1.376,0.66) 3(-1.376,-0.66) 4(-1.376,-1.917)
  rect 0.6x0.6 smd paste-1 mask+0: 5(4.166,-1.905) 6(4.166,-0.66) 7(4.166,0.66) 8(4.166,1.93)
  Top Layer region: 4.504,1.58 3.849,1.58 3.849,0.998 4.504,0.998 4.504,0.323 3.849,0.323 3.849,-0.322 4.504,-0.322 4.504,-0.997 3.849,-0.997 3.849,-1.58 4.504,-1.58 4.504,-2.255 -0.446,-2.255 -0.446,2.255 4.504,2.255
  silkscreen extent -2.23,-2.57 4.25,2.58, body extent -1.73,-2.49 4.3,2.49, height 1.04

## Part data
C1 C2 C8 C9 C10 C11: library part Cap, "Capacitor", Digikey Part Number=1276-1012-1-ND, Package=0603
C3: library part Cap, "Capacitor", Digikey Part Number=490-18620-1-ND, Package=1206
C4: library part Cap, "Capacitor", Digikey Part Number=587-2909-1-ND, Package=0603
C5 C15: library part Cap, "Capacitor", Digikey Part Number=490-16309-1-ND, Package=1210
C6: library part Cap, "Capacitor", Digikey Part Number=1276-CL10B152KC8WPJCCT-ND, Package=0603
C7: library part Cap, "Capacitor", Digikey Part Number=490-13329-1-ND, Package=0603
C12 C13 C14: library part Cap, "Capacitor", Digikey Part Number=490-6473-1-ND, Package=0805
F1: library part "Fuse 1", "Fuse", Digikey Part Number=749-MFU0603FF01000P1ATCT-ND, Package=0603
L1: library part Inductor, "Inductor", Digikey Part Number=732-74439384012CT-ND, Package="7.90mm x 7.60mm"
MOD1: library part A4988_STEPPER_MOTOR_DRIVER_CARRIER, Digikey Part Number=NILL
MOD2 MOD3 PAD1 PAD2 PAD3 PAD4 PAD5 PAD6 PAD7 PAD8: Digikey Part Number=NILL
P1: library part "HEADER 5X SMT", Digikey Part Number=455-B5B-PH-SM4-TBCT-ND
P2 P11 P12 P14 P15: library part "HEADER 3X SMT", Digikey Part Number=455-B3B-PH-SM4-TBCT-ND
P3: library part "HEADER 10X SMT", Dgikey Part Number=455-B10B-PH-SM4-TBCT-ND
P4 P5 P6: library part "Header 4", "Header, 4-Pin", Digikey Part Number=277-1142-ND
P7 P17: library part "Header 2", "Header, 2-Pin", Digikey Part Number=A138952-ND
P8: library part "Header 20X2", "Header, 20-Pin, Dual row", Digikey Part Number=S9175-ND
P9 P10: library part "Header 2", "Header, 2-Pin", Digikey Part Number=2-1376382-3
P13 P20 P22: library part "HEADER 2X SMT", Digikey Part Number=455-B2B-PH-SM4-TBCT-ND
P16: library part "HEADER 4X SMT", Digikey Part Number=455-B4B-PH-SM4-TBCT-ND
P18 P19: library part "Header 4", "Header, 4-Pin", Digikey Part Number=455-B4B-PH-K-ND
P21: library part "Header 5", "Header, 5-Pin", Digikey Part Number=455-B5B-PH-SM4-TBCT-ND
Q1: Digikey Part Number=296-35583-1-ND
Q2: Digikey Part Number=NTMFS5C670NLT1GOSCT-ND
Q3: library part NMOS-2, "N-Channel Power MOSFET", Digikey Part Number=IRF520SPBF-ND
Q4 Q5: Digikey Part Number=353-SIL05N06A-TPCT-ND
R1: library part Res1, "Resistor", Digikey Part Number=311-24.3KHRCT-ND, Package=0603
R2: library part Res1, "Resistor", Digikey Part Number=CSNL2010FT5L00CT-ND, Package=2010
R3 R8: library part Res1, "Resistor", Digikey Part Number=311-100KHRCT-ND, Package=0603
R4: library part Res1, "Resistor", Digikey Part Number=RMCF0603FT5K23CT-ND, Package=0603
R5: library part Res1, "Resistor", Digikey Part Number=541-21.0KHCT-ND, Package=0603
R6: library part Res1, "Resistor", Digikey Part Number=311-40.2KHRCT-ND, Package=0603
R7: library part Res1, "Resistor", Digikey Part Number=RMCF0603FT1K00CT-ND, Package=0603
R9 R10 R13 R14 R15 R16 R17 R18 R19 R20 R21 R22 R23 R26 R27: library part Res1, "Resistor", Digikey Part Number=RMCF0603JT10K0CT-ND, Package=0603
R11: library part Res1, "Resistor", Digikey Part Number=2019-RK73H1JTTD2202FCT-ND, Package=0603
R12: library part Res1, "Resistor", Digikey Part Number=P2.0KDBCT-ND, Package=0603
R24 R25: library part Res1, "Resistor", Digikey Part Number=541-5140-1-ND, Package=0603
U1: Digikey Part Number=296-LM5149RGYRCT-ND
U2 U3: Digikey Part Number=296-20697-1-ND

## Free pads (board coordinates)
  round 6 hole 3 paste+0 mask+0.051: 1(4,4) 2(116,4) 3(116,96) 4(4,96)

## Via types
v1: diameter 0.5, hole 0.3, Top Layer to Bottom Layer, 4470 vias

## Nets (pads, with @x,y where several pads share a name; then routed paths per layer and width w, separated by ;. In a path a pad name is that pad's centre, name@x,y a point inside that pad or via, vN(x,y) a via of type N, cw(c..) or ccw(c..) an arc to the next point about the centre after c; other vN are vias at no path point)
1A: MOD1.12 P16.2 | length 42.1
  Top Layer w1: P16.2@100.514,15.201 v1(100.514,20.193)
  Bottom Layer w1.2: MOD1.12@88.773,45.949 84.633,41.808 84.633,34.239 93.726,25.146 97.409,25.146 100.514,22.041 v1(100.514,20.193) v1(100.514,19.304)
1B: MOD1.11 P16.1 | length 39.8
  Top Layer w1: P16.1@102.514,15.201 v1(102.514,19.304) v1(102.514,20.193)
  Bottom Layer w1.2: MOD1.11@88.773,43.409 88.748,43.409 86.614,41.275 86.614,35.103 92.558,29.159 98.095,29.159 102.514,24.74 v1(102.514,20.193) v1(102.514,19.304)
2A: MOD1.13 P16.3 | length 47.5
  Top Layer w1: P16.3@98.514,15.201 v1(98.514,19.304) v1(98.514,20.193)
  Bottom Layer w1.2: MOD1.13@88.773,48.489 83.007,42.723 83.007,29.134 89.662,22.479 97.282,22.479 98.514,21.247 v1(98.514,20.193) v1(98.514,19.304)
2B: MOD1.14 P16.4 | length 50.8
  Top Layer w1: P16.4@96.517,15.201 v1(96.517,19.304) v1(96.517,20.193)
  Bottom Layer w1.2: MOD1.14@88.773,51.029 81.128,43.383 81.128,27.813 88.316,20.625 96.085,20.625 v1(96.517,20.193) v1(96.517,19.304)
+3V3: P8.1 R15.2 R16.2 R18.2 R19.2 R20.2 R21.2 R22.2 R23.2 | length 190.6
  Top Layer w0.5: R21.2@28.245,61.276 28.321,61.2 v1(28.321,60.452) ; R20.2@28.245,68.645 28.321,68.721 v1(28.321,69.469) ; v1(75.692,67.564) 75.692,68.415 R23.2@75.795,68.518 ; R22.2@75.796,76.014 75.819,76.037 v1(75.819,76.962) ; v1(108.331,84.455) 108.342,84.466 R16.2@108.342,86.157 ; v1(108.585,73.533) 108.585,72.683 R18.2@108.661,72.607 ; R19.2@108.661,65.366 108.712,65.315 v1(108.712,64.516) ; v1@115.708,84.593 R15.2@115.708,86.284
  Mid-Layer 2 w1.5: v1(28.321,60.452) v1(28.321,69.469) 28.321,73.533 30.099,75.311 30.099,87.122 31.623,88.646 33.147,88.646 34.544,90.043 34.544,95.387 35.423,96.266 41.402,96.266 43.688,93.98 v1(47.752,93.98)
  Bottom Layer w1.5: 45.72,94.005 47.752,94.005 69.063,94.005 74.549,88.519 74.549,84.861 75.717,83.693 79.131,83.693 80.01,82.814 80.01,77.724 ; v1@75.819,67.691 v1(75.819,76.962) 76.581,77.724 80.01,77.724 ; v1(108.712,64.516) 108.712,77.226 109.591,78.105 115.646,78.105 ; P8.1@115.646,74.13 115.646,78.105 ; 80.01,77.724 101.473,77.724 108.255,84.506 115.646,84.506 115.646,78.105
  other v1: 115.697,84.582 45.466,93.98 46.228,93.98 46.99,93.98
+3V3_ESP32: C8.2 C10.2 C13.2 MOD2.36 R9.2 R10.2 U2.1 U3.1 | length 113.3
  Top Layer w0.4: v1(48.641,29.21) 48.654,29.197 48.654,28.221 R9.2@48.666,28.208 ; U2.1@54.02,32.512 54.02,31.983 54.025,31.978 54.956,31.978 55.449,31.485 C8.2@55.499,31.485 55.505,31.49 56.636,31.49 v1(56.642,31.496) ; R10.2@60.325,28.183 v1(60.325,29.21) ; U3.1@65.704,32.512 65.704,31.983 65.709,31.978 66.64,31.978 67.133,31.485 C10.2@67.183,31.485 67.189,31.49 68.32,31.49 v1(68.326,31.496)
  Top Layer w1.1: v1(48.006,91.44) 48.006,78.88 MOD2.36@50.546,76.34
  Mid-Layer 2 w1.1: v1(48.006,91.44) 48.006,36.576 v1(48.26,36.322) v1(49.149,36.322) v1(50.038,36.322)
  Bottom Layer w1.1: v1(48.26,36.322) v1(49.149,36.322) v1(50.038,36.322) 51.435,34.925 ; v1(48.641,29.21) 49.53,29.21 51.435,31.115 51.435,34.925 ; v1(68.326,31.496) 67.31,31.496 65.024,29.21 v1(60.325,29.21) 58.928,29.21 v1(56.642,31.496) 53.213,34.925 51.435,34.925
+5V: C5.2 C9.2 C11.2 C12.2 C14.2 C15.2 MOD1.10 MOD2.39 MOD3.39 P1.1 P2.1 P3.1 P4.1 P4.2 P4.3 P4.4 P8.2 P8.4 P11.1 P12.1 P13.1 P14.1 P15.1 P21.1 R2.2 R17.2 U1.21 U2.14 U3.14 | length 68.5
  Top Layer w0.25: U1.21@19.195,62.626 19.21,62.641 19.643,62.641 20.832,63.83 21.209,63.83 v1(21.488,64.11)
  Top Layer w0.4: U2.14@54.02,26.772 54.02,26.675 54.025,26.67 v1(56.642,26.67) ; U3.14@65.704,26.772 65.704,26.792 65.709,26.797 v1(68.326,26.797) ; R17.2@79.338,36.043 79.375,36.079 v1(79.375,37.084)
  Top Layer w1: v1(71.603,89.129) C14.2@69.885,89.129 69.885,85.03 70.955,83.96 MOD3.39@72.44,83.96
  Top Layer w1.1: v1(50.181,89.043) C12.2@52.324,89.043 52.324,84.582 51.702,83.96 MOD2.39@50.546,83.96
  Mid-Layer 1 w0.25: v1(14.605,30.607) 14.605,31.166 14.986,31.547 20.753,31.547 23.368,34.162 23.368,62.967 22.512,63.823 21.775,63.823 v1(21.488,64.11)
  other v1: 103.632,5.842 104.394,5.842 103.632,6.604 104.394,6.604 103.632,7.366 104.394,7.366 13.081,18.161 13.843,18.161 14.605,18.161 15.367,18.161 16.129,18.161 16.891,18.161 17.653,18.161 18.415,18.161 19.177,18.161 19.939,18.161 20.701,18.161 21.463,18.161 22.225,18.161 13.081,18.923 13.843,18.923 14.605,18.923 15.367,18.923 16.129,18.923 16.891,18.923 17.653,18.923 18.415,18.923 19.177,18.923 19.939,18.923 20.701,18.923 21.463,18.923 22.225,18.923 13.081,19.685 13.843,19.685 14.605,19.685 15.367,19.685 16.129,19.685 16.891,19.685 17.653,19.685 18.415,19.685 19.177,19.685 19.939,19.685 20.701,19.685 21.463,19.685 22.225,19.685 13.081,20.447 13.843,20.447 14.605,20.447 15.367,20.447 16.129,20.447 16.891,20.447 17.653,20.447 18.415,20.447 19.177,20.447 19.939,20.447 20.701,20.447 21.463,20.447 22.225,20.447 15.367,21.209 16.129,21.209 16.891,21.209 17.653,21.209 18.415,21.209 19.177,21.209 19.939,21.209 20.701,21.209 21.463,21.209 22.225,21.209 15.367,21.971 16.129,21.971 16.891,21.971 17.653,21.971 18.415,21.971 19.177,21.971 19.939,21.971 20.701,21.971 21.463,21.971 22.225,21.971 15.367,22.733 16.129,22.733 16.891,22.733 17.653,22.733 18.415,22.733 19.177,22.733 19.939,22.733 20.701,22.733 21.463,22.733 22.225,22.733 15.367,23.495 16.129,23.495 16.891,23.495 17.653,23.495 18.415,23.495 19.177,23.495 19.939,23.495 20.701,23.495 21.463,23.495 22.225,23.495 15.367,24.257 16.129,24.257 16.891,24.257 17.653,24.257 18.415,24.257 19.177,24.257 19.939,24.257 20.701,24.257 21.463,24.257 22.225,24.257 15.367,25.019 16.129,25.019 16.891,25.019 17.653,25.019 18.415,25.019 19.177,25.019 19.939,25.019 20.701,25.019 21.463,25.019 22.225,25.019 15.367,25.781 16.129,25.781 16.891,25.781 17.653,25.781 18.415,25.781 19.177,25.781 19.939,25.781 20.701,25.781 21.463,25.781 22.225,25.781 103.886,26.162 104.648,26.162 15.367,26.543 16.129,26.543 16.891,26.543 17.653,26.543 18.415,26.543 19.177,26.543 19.939,26.543 20.701,26.543 21.463,26.543 22.225,26.543 103.886,26.924 104.648,26.924 15.367,27.305 16.129,27.305 16.891,27.305 17.653,27.305 18.415,27.305 19.177,27.305 19.939,27.305 20.701,27.305 21.463,27.305 22.225,27.305 103.886,27.686 104.648,27.686 15.367,28.067 16.129,28.067 16.891,28.067 17.653,28.067 18.415,28.067 19.177,28.067 19.939,28.067 20.701,28.067 21.463,28.067 22.225,28.067 103.886,36.576 104.648,36.576 103.886,37.338 104.648,37.338 103.886,38.1 104.648,38.1 103.886,46.228 104.648,46.228 103.886,46.99 104.648,46.99 103.886,47.752 104.648,47.752 103.886,56.388 104.648,56.388 103.886,57.15 104.648,57.15 103.886,57.912 104.648,57.912 103.886,66.04 104.648,66.04 103.886,66.802 104.648,66.802 103.886,67.564 104.648,67.564 103.632,76.2 104.394,76.2 103.632,76.962 104.394,76.962 103.632,77.724 104.394,77.724 103.886,86.106 104.648,86.106 103.886,86.868 104.648,86.868 103.886,87.63 104.648,87.63 50.927,89.027 70.866,89.154 103.759,96.317 104.521,96.317 103.759,97.079 104.521,97.079 103.759,97.841 104.521,97.841
+BATT: C3.2 F1.2 MOD1.16 P6.1 P6.2 P7.1 P17.1 Q1.5 Q1.6 Q1.7 Q1.8 R13.2 R14.2 U1.12 U1.19 | length 122.6
  Top Layer w0.2: U1.19@19.195,61.626 20.351,61.626 v1(20.574,61.849)
  Top Layer w0.5: R13.2@76.327,87.06 76.392,86.995 v1(77.724,86.995) ; v1(80.772,68.326) F1.2@82.256,68.326 ; v1(83.312,87.122) 84.647,87.122 R14.2@84.709,87.06
  Mid-Layer 1 w0.5: v1(16.764,57.912) 18.034,57.912 19.609,59.487 19.609,61.214 20.244,61.849 v1(20.574,61.849)
  Mid-Layer 2 w1.5: v1@77.724,88.519 v1(77.724,88.392) v1(77.724,87.694) 77.724,87.376 74.619,84.271 74.619,70.542 76.835,68.326 v1(78.74,68.326) v1(79.756,68.326) v1(80.772,68.326)
  Bottom Layer w1.5: P17.1@25.375,94.339 27.375,96.339 32.312,96.339 72.952,96.339 77.724,91.567 v1(77.724,88.392) v1(77.724,87.694) 77.724,87.122 v1@83.185,87.122 ; v1(78.74,68.326) v1(79.756,68.326) v1(80.772,68.326) 83.058,68.326 88.773,62.611 MOD1.16@88.773,56.109
  other v1: 3.302,47.244 4.318,47.244 5.334,47.244 6.35,47.244 7.366,47.244 8.382,47.244 9.398,47.244 10.414,47.244 11.43,47.244 12.446,47.244 2.286,48.26 3.302,48.26 4.318,48.26 5.334,48.26 6.35,48.26 8.89,48.26 9.652,48.26 10.414,48.26 11.176,48.26 11.938,48.26 8.89,49.022 9.652,49.022 10.414,49.022 11.176,49.022 11.938,49.022 1.27,49.276 2.286,49.276 3.302,49.276 4.318,49.276 5.334,49.276 6.35,49.276 8.89,49.784 9.652,49.784 10.414,49.784 11.176,49.784 11.938,49.784 1.27,50.292 2.286,50.292 3.302,50.292 4.318,50.292 5.334,50.292 6.35,50.292 8.89,50.546 9.652,50.546 10.414,50.546 11.176,50.546 11.938,50.546 1.27,51.308 2.286,51.308 3.302,51.308 4.318,51.308 5.334,51.308 6.35,51.308 8.89,51.308 9.652,51.308 10.414,51.308 11.176,51.308 11.938,51.308 8.89,52.07 9.652,52.07 10.414,52.07 11.176,52.07 11.938,52.07 1.27,52.324 2.286,52.324 3.302,52.324 4.318,52.324 5.334,52.324 6.35,52.324 1.27,53.34 2.286,53.34 3.302,53.34 4.318,53.34 5.334,53.34 6.35,53.34 7.366,53.34 8.382,53.34 9.398,53.34 10.414,53.34 11.43,53.34 12.446,53.34 13.462,53.34 1.27,54.356 2.286,54.356 3.302,54.356 4.318,54.356 5.334,54.356 6.35,54.356 7.366,54.356 8.382,54.356 9.398,54.356 10.414,54.356 11.43,54.356 12.446,54.356 13.462,54.356 1.27,55.372 2.286,55.372 3.302,55.372 4.318,55.372 5.334,55.372 6.35,55.372 7.366,55.372 8.382,55.372 9.398,55.372 10.414,55.372 1.27,56.388 2.286,56.388 3.302,56.388 4.318,56.388 5.334,56.388 6.35,56.388 7.366,56.388 8.382,56.388 9.398,56.388 1.27,57.404 2.286,57.404 3.302,57.404 4.318,57.404 5.334,57.404 6.35,57.404 7.366,57.404 8.382,57.404 9.398,57.404 1.27,58.42 2.286,58.42 3.302,58.42 4.318,58.42 5.334,58.42 6.35,58.42 7.366,58.42 8.382,58.42 9.398,58.42 1.27,59.436 2.286,59.436 3.302,59.436 4.318,59.436 5.334,59.436 6.35,59.436 7.366,59.436 8.382,59.436 9.398,59.436 1.27,60.452 2.286,60.452 3.302,60.452 4.318,60.452 5.334,60.452 6.35,60.452 7.366,60.452 8.382,60.452 9.398,60.452 1.27,61.468 2.286,61.468 3.302,61.468 4.318,61.468 5.334,61.468 6.35,61.468 7.366,61.468 8.382,61.468 9.398,61.468 1.27,62.484 2.286,62.484 3.302,62.484 4.318,62.484 5.334,62.484 6.35,62.484 7.366,62.484 8.382,62.484 9.398,62.484 1.27,63.5 2.286,63.5 3.302,63.5 4.318,63.5 5.334,63.5 6.35,63.5 7.366,63.5 8.382,63.5 9.398,63.5 1.27,64.516 2.286,64.516 3.302,64.516 4.318,64.516 5.334,64.516 6.35,64.516 7.366,64.516 8.382,64.516 9.398,64.516 1.27,65.532 2.286,65.532 3.302,65.532 4.318,65.532 5.334,65.532 6.35,65.532 7.366,65.532 8.382,65.532 9.398,65.532 1.27,66.548 2.286,66.548 3.302,66.548 4.318,66.548 5.334,66.548 6.35,66.548 7.366,66.548 8.382,66.548 9.398,66.548 1.27,67.564 2.286,67.564 3.302,67.564 4.318,67.564 5.334,67.564 6.35,67.564 7.366,67.564 8.382,67.564 9.398,67.564 1.27,68.58 2.286,68.58 3.302,68.58 4.318,68.58 5.334,68.58 6.35,68.58 7.366,68.58 8.382,68.58 9.398,68.58 1.27,69.596 2.286,69.596 3.302,69.596 4.318,69.596 5.334,69.596 6.35,69.596 7.366,69.596 8.382,69.596 9.398,69.596 1.27,70.612 2.286,70.612 3.302,70.612 4.318,70.612 5.334,70.612 6.35,70.612 7.366,70.612 8.382,70.612 9.398,70.612 10.414,70.612 1.27,71.628 2.286,71.628 3.302,71.628 4.318,71.628 5.334,71.628 6.35,71.628 7.366,71.628 8.382,71.628 9.398,71.628 10.414,71.628 11.43,71.628 1.27,72.644 2.286,72.644 3.302,72.644 4.318,72.644 5.334,72.644 6.35,72.644 7.366,72.644 8.382,72.644 9.398,72.644 10.414,72.644 11.43,72.644 12.446,72.644 1.27,73.66 2.286,73.66 3.302,73.66 4.318,73.66 5.334,73.66 6.35,73.66 7.366,73.66 8.382,73.66 9.398,73.66 10.414,73.66 11.43,73.66 12.446,73.66 13.462,73.66 1.27,74.676 2.286,74.676 3.302,74.676 4.318,74.676 5.334,74.676 6.35,74.676 7.366,74.676 8.382,74.676 9.398,74.676 10.414,74.676 11.43,74.676 12.446,74.676 13.462,74.676 14.478,74.676 1.27,75.692 2.286,75.692 3.302,75.692 4.318,75.692 5.334,75.692 6.35,75.692 7.366,75.692 8.382,75.692 9.398,75.692 10.414,75.692 11.43,75.692 12.446,75.692 13.462,75.692 14.478,75.692 15.494,75.692 1.27,76.708 2.286,76.708 3.302,76.708 4.318,76.708 5.334,76.708 6.35,76.708 7.366,76.708 8.382,76.708 1.27,77.724 2.286,77.724 3.302,77.724 4.318,77.724 5.334,77.724 6.35,77.724 7.366,77.724 8.382,77.724 9.398,77.724 10.414,77.724 11.43,77.724 12.446,77.724 13.462,77.724 14.478,77.724 15.494,77.724 16.51,77.724 1.27,78.74 2.286,78.74 3.302,78.74 4.318,78.74 5.334,78.74 6.35,78.74 7.366,78.74 8.382,78.74 9.398,78.74 10.414,78.74 11.43,78.74 12.446,78.74 13.462,78.74 14.478,78.74 15.494,78.74 16.51,78.74 17.526,78.74 1.27,79.756 2.286,79.756 3.302,79.756 4.318,79.756 5.334,79.756 6.35,79.756 7.366,79.756 8.382,79.756 9.398,79.756 10.414,79.756 11.43,79.756 12.446,79.756 13.462,79.756 14.478,79.756 15.494,79.756 16.51,79.756 17.526,79.756 1.27,80.772 2.286,80.772 3.302,80.772 4.318,80.772 5.334,80.772 6.35,80.772 7.366,80.772 8.382,80.772 9.398,80.772 12.446,80.772 13.462,80.772 14.478,80.772 17.526,80.772 1.27,81.788 2.286,81.788 3.302,81.788 4.318,81.788 5.334,81.788 6.35,81.788 7.366,81.788 8.382,81.788 9.398,81.788 13.462,81.788 1.27,82.804 2.286,82.804 3.302,82.804 4.318,82.804 5.334,82.804 6.35,82.804 7.366,82.804 8.382,82.804 9.398,82.804 12.446,82.804 13.462,82.804 14.478,82.804 17.526,82.804 18.542,82.804 1.27,83.82 2.286,83.82 3.302,83.82 4.318,83.82 5.334,83.82 6.35,83.82 7.366,83.82 8.382,83.82 9.398,83.82 10.414,83.82 11.43,83.82 12.446,83.82 13.462,83.82 14.478,83.82 15.494,83.82 16.51,83.82 17.526,83.82 18.542,83.82 19.558,83.82 1.27,84.836 2.286,84.836 3.302,84.836 4.318,84.836 5.334,84.836 6.35,84.836 7.366,84.836 8.382,84.836 9.398,84.836 10.414,84.836 11.43,84.836 12.446,84.836 13.462,84.836 14.478,84.836 15.494,84.836 16.51,84.836 17.526,84.836 18.542,84.836 19.558,84.836 20.574,84.836 1.27,85.852 2.286,85.852 3.302,85.852 4.318,85.852 5.334,85.852 6.35,85.852 7.366,85.852 8.382,85.852 9.398,85.852 10.414,85.852 11.43,85.852 12.446,85.852 13.462,85.852 14.478,85.852 15.494,85.852 16.51,85.852 17.526,85.852 18.542,85.852 19.558,85.852 20.574,85.852 21.59,85.852 1.27,86.868 2.286,86.868 3.302,86.868 4.318,86.868 5.334,86.868 6.35,86.868 7.366,86.868 8.382,86.868 9.398,86.868 10.414,86.868 11.43,86.868 12.446,86.868 13.462,86.868 14.478,86.868 15.494,86.868 16.51,86.868 17.526,86.868 18.542,86.868 19.558,86.868 20.574,86.868 21.59,86.868 22.606,86.868 1.27,87.884 2.286,87.884 3.302,87.884 4.318,87.884 5.334,87.884 6.35,87.884 7.366,87.884 8.382,87.884 9.398,87.884 10.414,87.884 11.43,87.884 12.446,87.884 13.462,87.884 14.478,87.884 15.494,87.884 16.51,87.884 17.526,87.884 18.542,87.884 19.558,87.884 20.574,87.884 21.59,87.884 22.606,87.884 23.622,87.884 2.286,88.9 3.302,88.9 4.318,88.9 5.334,88.9 6.35,88.9 7.366,88.9 8.382,88.9 14.478,88.9 18.542,88.9 19.558,88.9 20.574,88.9 21.59,88.9 22.606,88.9 3.302,89.916 4.318,89.916 5.334,89.916 6.35,89.916 7.366,89.916 8.382,89.916 9.398,89.916 10.414,89.916 11.43,89.916 12.446,89.916 13.462,89.916 14.478,89.916 15.494,89.916 16.51,89.916 17.526,89.916 18.542,89.916 19.558,89.916 20.574,89.916 21.59,89.916 22.606,89.916 23.622,89.916 24.638,89.916 25.654,89.916 4.318,90.932 5.334,90.932 6.35,90.932 7.366,90.932 8.382,90.932 9.398,90.932 10.414,90.932 11.43,90.932 12.446,90.932 13.462,90.932 14.478,90.932 15.494,90.932 16.51,90.932 17.526,90.932 18.542,90.932 19.558,90.932 21.59,90.932 22.606,90.932 23.622,90.932 24.638,90.932 25.654,90.932 26.67,90.932 5.334,91.948 6.35,91.948 7.366,91.948 8.382,91.948 9.398,91.948 10.414,91.948 11.43,91.948 12.446,91.948 13.462,91.948 14.478,91.948 15.494,91.948 16.51,91.948 17.526,91.948 18.542,91.948 19.558,91.948 21.59,91.948 22.606,91.948 23.622,91.948 24.638,91.948 25.654,91.948 26.67,91.948 6.35,92.964 7.366,92.964 8.382,92.964 9.398,92.964 19.558,92.964 21.59,92.964 22.606,92.964 23.622,92.964 7.366,93.98 8.382,93.98 9.398,93.98 19.558,93.98 21.59,93.98 22.606,93.98 23.622,93.98 8.382,94.996 9.398,94.996 19.558,94.996 21.59,94.996 22.606,94.996 23.622,94.996
ESP32-1_GPIO_4: MOD2.26 U2.4 | length 19.1
  Top Layer w0.25: U2.4@52.07,32.512 v1(52.07,36.322)
  Mid-Layer 2 w0.2: MOD2.26@50.546,50.94 52.07,49.416 v1(52.07,36.322)
ESP32-1_GPIO_5: MOD2.27 U3.4 | length 32.1
  Top Layer w0.25: v1(63.739,35.829) 63.739,32.527 U3.4@63.754,32.512
  Mid-Layer 2 w0.2: MOD2.27@50.546,53.48 52.47,51.556 52.47,37.446 54.087,35.829 v1(63.739,35.829)
ESP32-1_GPIO_11: MOD2.1 U2.3 | length 80.2
  Top Layer w0.2: v1@52.713,31.123 U2.3@52.713,32.504
  Mid-Layer 1 w0.2: MOD2.1@32.766,86.5 29.21,82.944 29.21,35.687 31.877,33.02 52.324,33.02 53.057,32.287 53.057,31.467 v1(52.705,31.115)
ESP32-1_GPIO_12: MOD2.2 U2.2 | length 77.6
  Top Layer w0.2: U2.2@53.37,32.512 53.37,31.466 v1(53.721,31.115)
  Mid-Layer 1 w0.2: MOD2.2@32.766,83.96 29.642,80.836 29.642,79.333 29.642,37.522 29.642,35.89 32.073,33.459 52.451,33.459 53.467,32.443 53.467,31.385 53.721,31.131 v1(53.721,31.115)
ESP32-1_GPIO_13: MOD2.4 U3.3 | length 83.2
  Top Layer w0.2: v1(64.389,31.115) 64.397,31.123 64.397,32.504 U3.3@64.404,32.512
  Mid-Layer 1 w0.2: MOD2.4@32.766,78.88 30.042,76.156 30.042,36.125 32.308,33.859 63.804,33.859 64.643,33.02 64.643,31.369 v1(64.389,31.115)
ESP32-1_GPIO_14: MOD2.5 U3.2 | length 80.7
  Top Layer w0.2: U3.2@65.054,32.512 65.054,31.466 v1(65.405,31.115)
  Mid-Layer 1 w0.2: MOD2.5@32.766,76.34 30.442,74.016 30.442,36.36 32.512,34.29 64.008,34.29 65.151,33.147 65.151,31.385 65.405,31.131 v1(65.405,31.115)
ESP32-1_GPIO_15: MOD1.7 MOD2.6 | length 91.2
  Mid-Layer 1 w0.2: MOD2.6@32.766,73.8 32.436,73.8 30.842,72.206 30.842,36.537 32.689,34.69 75.203,34.69 77.597,37.084 77.597,39.345 MOD1.7@76.073,40.869
ESP32-1_GPIO_16: MOD1.8 MOD2.7 | length 83.2
  Mid-Layer 1 w0.2: MOD2.7@32.766,71.26 31.242,69.736 31.242,36.703 32.855,35.09 74.892,35.09 76.073,36.271 MOD1.8@76.073,38.329
ESP32-1_GPIO_17: MOD2.9 P8.10 R20.1 | length 153.6
  Top Layer w0.2: R20.1@28.245,67.245 31.701,67.245 MOD2.9@32.766,66.18
  Mid-Layer 2 w0.2: MOD2.9@32.766,66.18 29.496,62.91 29.496,35.659 32.22,32.935 94.573,32.935 98.806,28.702 104.521,28.702 111.506,35.687 111.506,62.37 P8.10@113.106,63.97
